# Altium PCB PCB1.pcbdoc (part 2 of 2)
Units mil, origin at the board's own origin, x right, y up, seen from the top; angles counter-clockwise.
Board outline 2755.9 x 2755.9 mil, 4 copper layers (Top Layer, GND02, PWR03, Bottom Layer), stack 64.1 mil thick; 209 components, 118 nets, 572 pads, 665 vias.
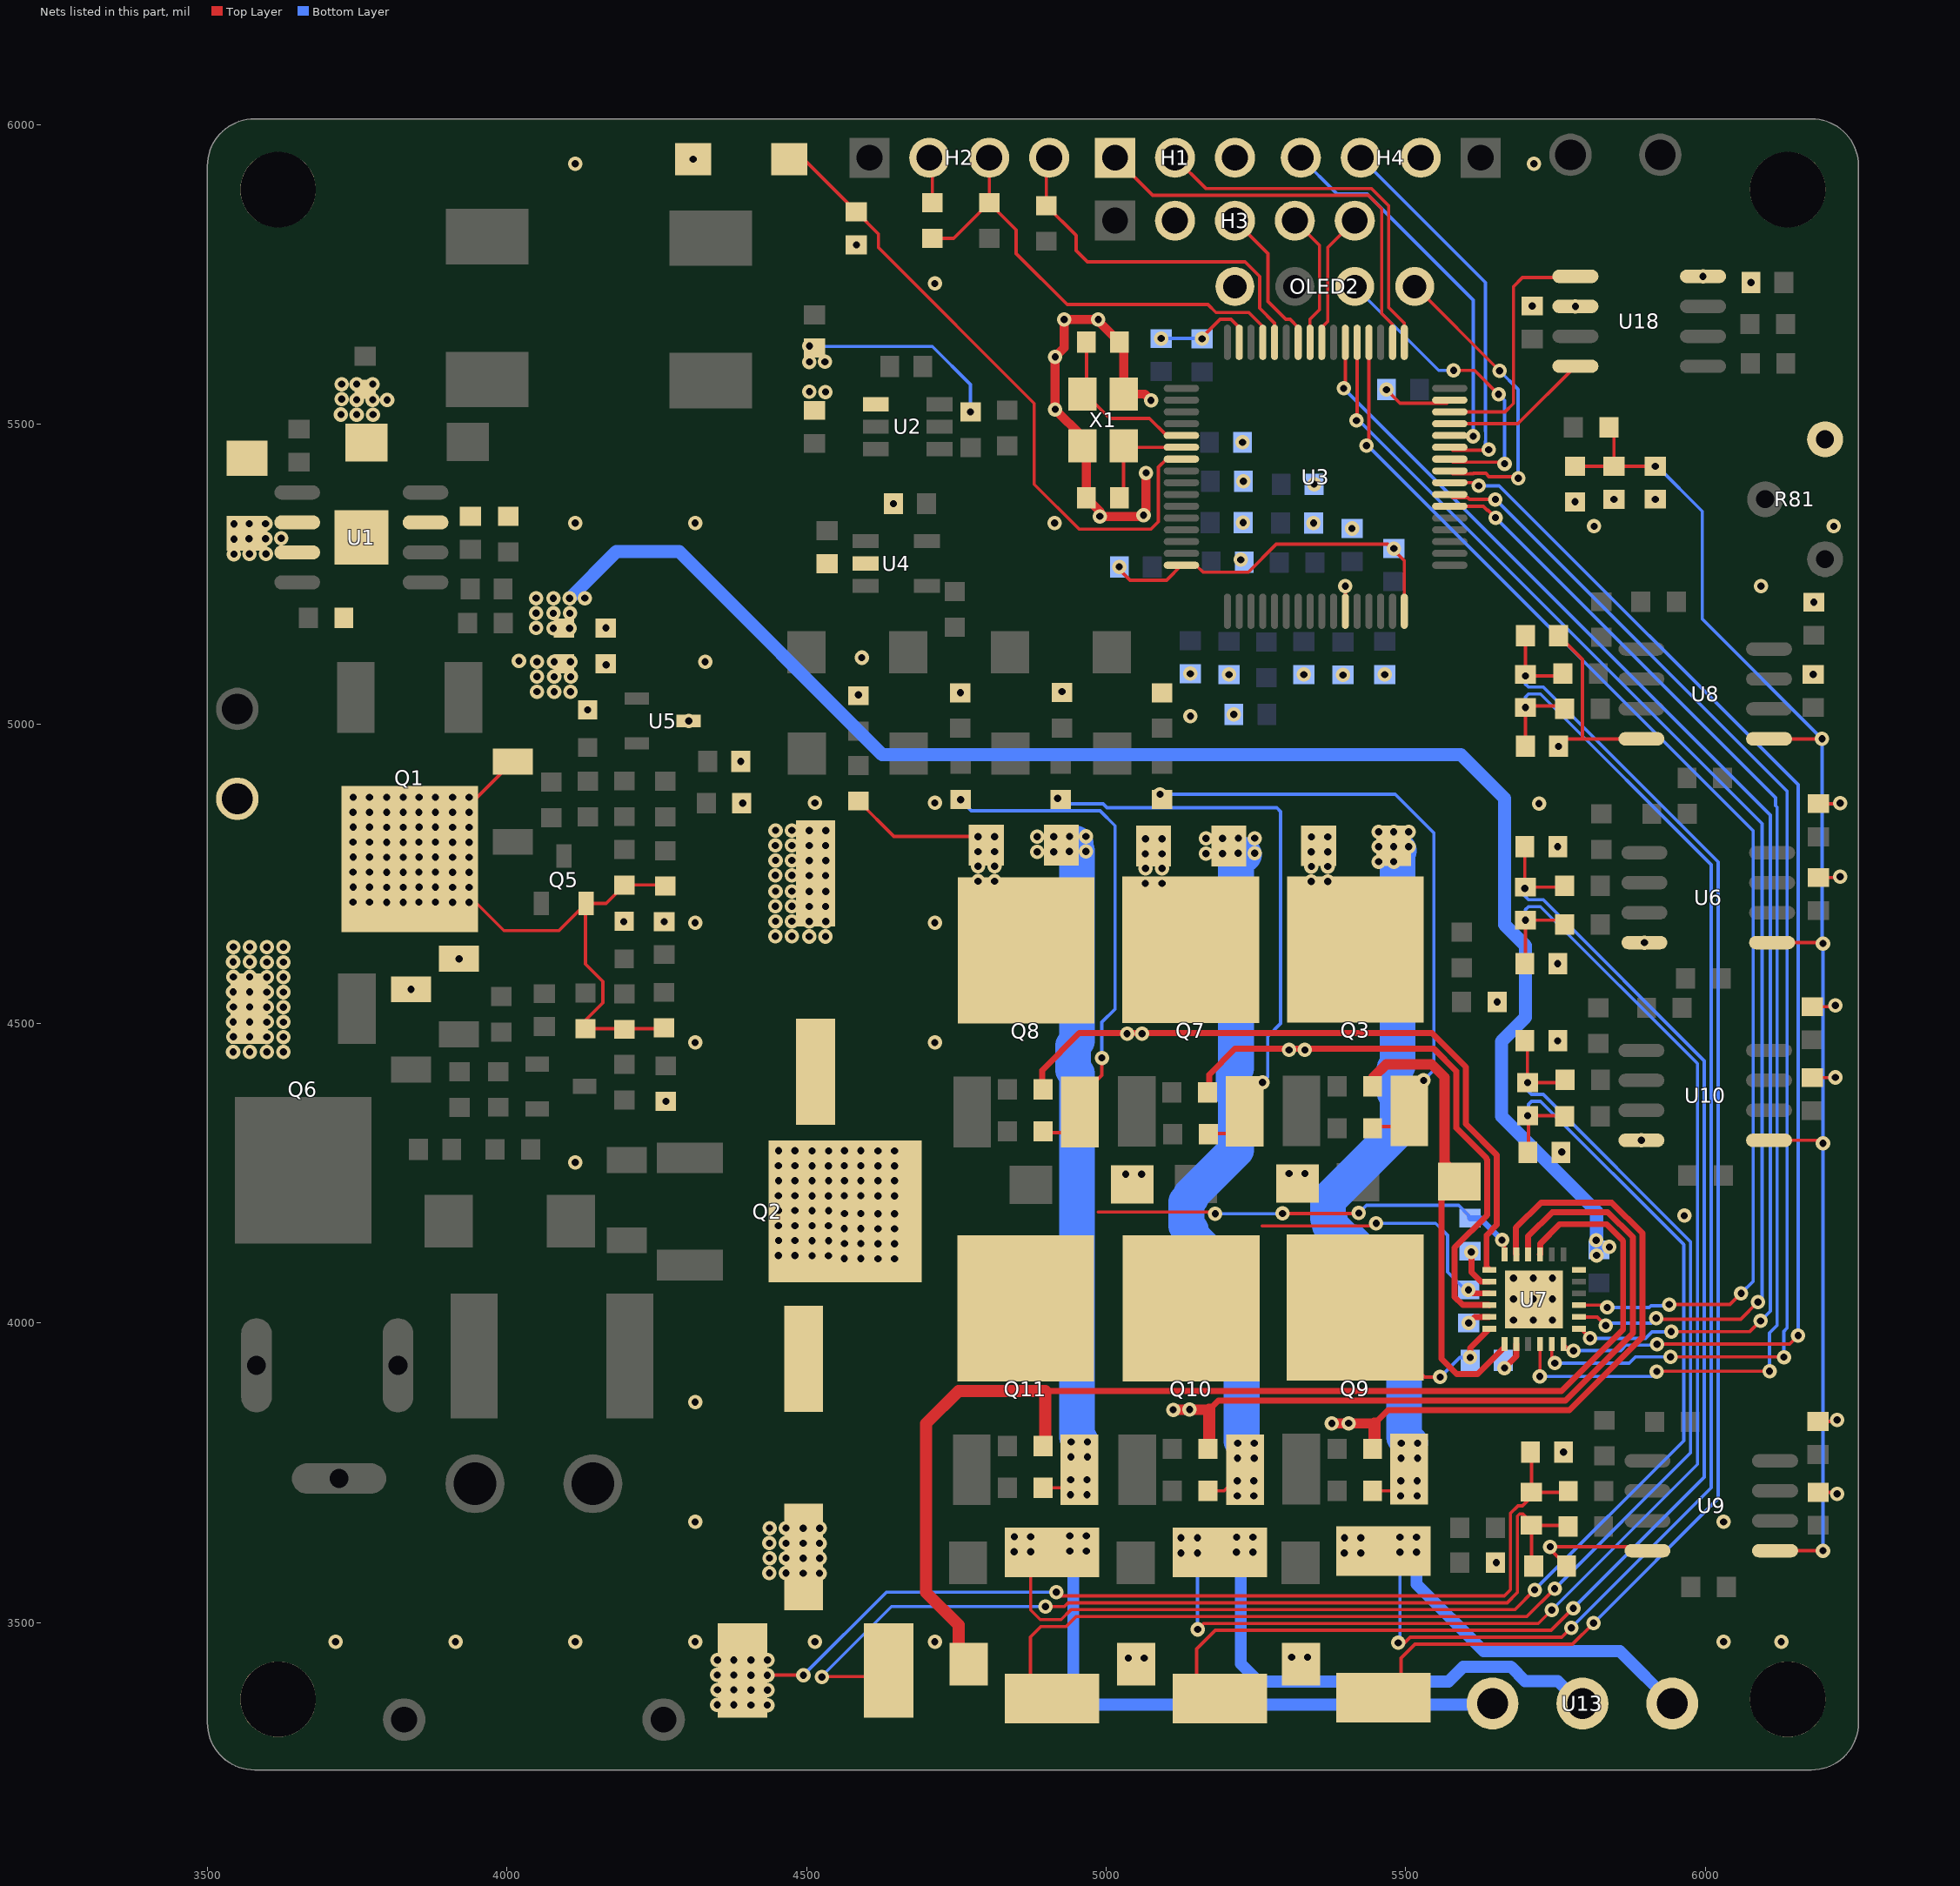
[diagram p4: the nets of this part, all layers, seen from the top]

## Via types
v1: diameter 24, hole 12, Top Layer to Bottom Layer, 665 vias

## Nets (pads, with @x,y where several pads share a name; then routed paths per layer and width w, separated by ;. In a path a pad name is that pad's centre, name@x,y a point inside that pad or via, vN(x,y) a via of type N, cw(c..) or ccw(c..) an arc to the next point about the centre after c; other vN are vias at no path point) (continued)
AGND: C18.2 C19.2 C21.1 C33.1 C34.1 C35.1 C36.1 C38.1 C39.1 C40.1 C41.1 C42.1 C44.1 C45.1 C46.1 C47.1 C48.1 C50.1 C51.1 C52.1 C53.1 C54.1 C56.1 C57.1 C58.1 C61.1 C63.1 C64.1 C68.1 C69.1 C70.1 R12.1 R37.1 R65.1 R67.1 R69.1 R71.1 R72.1 R73.1 R81.3 SCREW3.1 U3.27 U6.4 U8.4 U9.4 U10.4 | length 806
  Top Layer w5.5: U3.27@5399.3,5188.1 v1(5399.3,5230) ; v1(5755,4962.6) C45.1@5755.1,4962.7 ; C45.1@5755.1,4969.5 C45.1@5755.1,4962.7 ; C44.1@5755.1,5147.4 5795,5107.6 5795,4975 ; C39.1@5768.7,3594.6 5741.2,3622.1 v1(5741.2,3626.5) 5897,3626.5 U9.4@5903.5,3620 ; U8.4@5893.5,4975 5795,4975 ; C54.1@6178.7,4409.6 6216.8,4409.6 v1(6217.2,4410) ; C53.1@6178.7,4527.9 6215.1,4527.9 v1(6217.2,4530) ; C33.1@6188.4,3835.7 6219.3,3835.7 v1@6220,3835 ; C36.1@6188.5,3717.5 6217.5,3717.5 v1(6220,3715) ; C48.1@6188.7,4743.5 6223.5,4743.5 v1(6225,4745) ; C47.1@6188.7,4866.8 6223.2,4866.8 v1@6225,4865 ; C45.1@5755.1,4962.7 5767.4,4975 5795,4975
  other v1: 6030.7,3468.2 6126.9,3468.2 5651.3,3600 6030.7,3668.2 5763.5,3784.6 6220,3838.3 5965,4179.2 5760.5,4285.5 5893.5,4305 5753.8,4471.1 5652.7,4535.8 5753.8,4600 5898.5,4635 5753.8,4795 5722.5,4866.9 6225,4867.7 5140.8,5012.8 5213.3,5015.8 4586.5,5048.6 4756.7,5052 4926.3,5054 5205,5082.4 5330,5082.3 5395.3,5081.7 5465,5082.4 6180.1,5082.6 5140.4,5083.8 4330.8,5103.6 4592.2,5110.6 4165.1,5160.5 6181.2,5203.1 6092.9,5230 5224.8,5274 5410.4,5326.2 5814.6,5330 6214.6,5330 5346.3,5335.1 5228.7,5336.1 5782.7,5370.7 5847.6,5374.9 5916.6,5375 5347.2,5400.1 5229.2,5405 5227.7,5470
BSTA: C29.2 U7.20 | length 41
  Top Layer w10: v1@5670,3930 5684.7,3944.7 U7.20@5684.7,3964.9
  other v1: 5665,3925
BSTB: C30.1 U7.17 | length 38.5
  Top Layer w10: v1(5605.2,4000.1) 5615.3,4010.2 U7.17@5639.5,4010.2
BSTC: C31.1 U7.14 | length 70.1
  Top Layer w10: v1(5609.7,4118.6) 5609.7,4084.8 5625.3,4069.2 U7.14@5639.5,4069.2
DCBUS: C2.1 C5.1 C13.2 C59.1 C60.1 C62.1 D6.1 Q1.2 Q2.2 Q3.2 Q5.2 Q7.2 Q8.2 R8.2 R9.2 R10.2 R15.2 R23.2 R70.2 U1.2 U1.3 | length 1082.4
  Top Layer w5.5: v1(3936.7,4702.3) 3947.7,4702.3 3995,4655 4086.8,4655 Q5.2@4131,4699.3 ; v1(3936.7,4852.3) 3936.7,4863.6 D6.1@4010,4936.9 ; R8.2@4262.3,4492.6 4261,4491.4 R9.2@4131,4491.4 4131,4505.4 4160,4534.4 4160,4570 4131,4599 Q5.2@4131,4699.3 ; R23.2@4264.1,4729.2 4262.2,4731.1 R15.2@4195.9,4731.1 4165.5,4700.6 Q5.2@4132.4,4700.6 Q5.2@4131,4699.3 ; R70.2@4586.5,4871.3 4645.8,4812 v1(4786.4,4812)
  other v1: 4619.4,4107.3 4646.7,4107.3 4563,4107.6 4590.7,4107.6 4509.4,4112.3 4536.7,4112.3 4453,4112.6 4480.7,4112.6 4619.4,4132.4 4647,4132.4 4563.3,4132.7 4590.7,4132.7 4509.4,4137.4 4537,4137.4 4453.3,4137.7 4480.7,4137.7 4619.4,4157.3 4646.7,4157.3 4563,4157.6 4590.7,4157.6 4509.4,4162.3 4536.7,4162.3 4453,4162.6 4480.7,4162.6 4619.4,4182.4 4647,4182.4 4563.3,4182.7 4590.7,4182.7 4509.4,4187.4 4537,4187.4 4453.3,4187.7 4480.7,4187.7 4509.4,4212.3 4536.7,4212.3 4619.4,4212.3 4646.7,4212.3 4453,4212.6 4480.7,4212.6 4563,4212.6 4590.7,4212.6 4509.4,4237.4 4537,4237.4 4619.4,4237.4 4647,4237.4 4453.3,4237.7 4480.7,4237.7 4563.3,4237.7 4590.7,4237.7 4509.4,4262.3 4536.7,4262.3 4619.4,4262.3 4646.7,4262.3 4453,4262.6 4480.7,4262.6 4563,4262.6 4590.7,4262.6 4509.4,4287.4 4537,4287.4 4619.4,4287.4 4647,4287.4 4453.3,4287.7 4480.7,4287.7 4563.3,4287.7 4590.7,4287.7 3799.4,4702.3 3826.7,4702.3 3909.4,4702.3 3743,4702.6 3770.7,4702.6 3853,4702.6 3880.7,4702.6 3799.4,4727.4 3827,4727.4 3909.4,4727.4 3937,4727.4 3743.3,4727.7 3770.7,4727.7 3853.3,4727.7 3880.7,4727.7 5065.5,4733.7 5093.2,4733.7 4786.2,4737.4 4813.8,4737.4 5342.4,4736.9 5370.1,4736.9 3799.4,4752.3 3826.7,4752.3 3909.4,4752.3 3936.7,4752.3 3743,4752.6 3770.7,4752.6 3853,4752.6 3880.7,4752.6 5065.8,4758.8 5093.2,4758.8 5342.7,4762 5370.1,4762 4786.4,4762.6 4813.8,4762.6 3799.4,4777.4 3827,4777.4 3909.4,4777.4 3937,4777.4 3743.3,4777.7 3770.7,4777.7 3853.3,4777.7 3880.7,4777.7 5065.5,4783.2 5093.2,4783.2 5342.4,4786.3 5370.1,4786.3 4786.2,4786.9 4813.8,4786.9 3799.4,4802.3 3826.7,4802.3 3909.4,4802.3 3936.7,4802.3 3743,4802.6 3770.7,4802.6 3853,4802.6 3880.7,4802.6 5065.8,4808.3 5093.2,4808.3 5342.7,4811.4 5370.1,4811.4 4813.8,4812 3799.4,4827.4 3827,4827.4 3909.4,4827.4 3937,4827.4 3743.3,4827.7 3770.7,4827.7 3853.3,4827.7 3880.7,4827.7 3799.4,4852.3 3826.7,4852.3 3909.4,4852.3 3743,4852.6 3770.7,4852.6 3853,4852.6 3880.7,4852.6 3799.4,4877.4 3827,4877.4 3909.4,4877.4 3937,4877.4 3743.3,4877.7 3770.7,4877.7 3853.3,4877.7 3880.7,4877.7 3544.3,5283.2 3570.3,5283.6 3597.7,5283.6 3544.3,5308.3 3569.4,5309.1 3597.1,5309.1 3623.1,5309.8 3544.4,5333.7 3569.7,5334.2 3597.1,5334.2
FDCAN1_RX: U3.45 U18.4 | length 249.4
  Top Layer w5.5: U3.45@5573.6,5501.1 5687.3,5501.1 U18.4@5783.3,5597
FDCAN1_TX: U3.46 U18.1 | length 417.6
  Top Layer w5.5: U3.46@5573.6,5520.8 5665.8,5520.8 5680,5535 5680,5730 5695,5745 5781.3,5745 U18.1@5783.3,5747
GHA: D3.2 R84.1 U7.19 | length 778
  Top Layer w10: D3.2@5590.4,4224.2 5579.2,4224.2 5560,4205 5560,3940 5585,3915 5620,3915 5665.1,3960.1 U7.19@5665.1,3964.9
  Top Layer w17: R84.1@5446.5,4394.5 5446.5,4410.7 5467.7,4431.9 5543.1,4431.9 5565,4410 5565,4266.5 D3.2@5593,4238.4
GHB: D7.2 R61.1 U7.16 | length 957.1
  Top Layer w10: R61.1@5171.9,4387.8 5171.9,4414.7 5215.1,4457.9 5547.1,4457.9 5584.5,4420.5 5584.5,4325.5 5635,4275 5635,4273.7 5636.2,4272.5 5636.2,4180.2 5581.8,4125.8 5581.8,4043.6 5595.3,4030.1 5639.2,4030.1 U7.16@5639.5,4029.8
  other v1: 5305.5,4249.4 5332,4249.4 5305.2,4455.9 5331.7,4455.9
GHC: D8.2 R63.1 U7.13 | length 1155.4
  Top Layer w10: R63.1@4897.6,4393.1 4893.4,4397.2 4893.4,4421.9 4955.4,4483.8 4980.5,4483.8 ccw(c4980.5,4499.8) 4982.01,4483.87 ; 4982,4483.9 5543.7,4483.9 5600.5,4427.1 5600.5,4332.1 5652.2,4280.4 5652.2,4163.7 5635,4146.5 5635,4093.4 U7.13@5639.5,4088.9
  other v1: 5032.6,4248.5 5059.1,4248.5 5035,4483 5060,4483
GLA: D9.2 R75.1 U7.11 | length 1088.3
  Top Layer w10: 5447.9,3832.3 5470.3,3854.7 5773.3,3854.7 5895,3976.4 5895,4150 5844,4201 5726,4201 5684.2,4159.2 5684.2,4115 U7.11@5684.7,4114.5
  Top Layer w17: v1(5376.8,3832.3) 5447.9,3832.3
  Top Layer w20: R75.1@5447.9,3789.6 5447.9,3832.3
  other v1: 5309.7,3442.2 5336.2,3442.2 5405,3832.7
GLB: D10.2 R77.1 U7.10 | length 1280.3
  Top Layer w10: 5172.1,3855.3 5187.5,3870.7 5766.6,3870.7 5879,3983 5879,4143.4 5837.4,4185 5744.6,4185 5704.4,4144.9 U7.10@5704.4,4114.5
  Top Layer w17: v1(5111.9,3855.3) 5172.1,3855.3
  Top Layer w20: R77.1@5172.1,3794.2 5172.1,3855.3
  other v1: 5037.2,3440.8 5063.7,3440.8 5139.3,3855.8
GLC: D11.2 R79.1 U7.9 | length 2057
  Top Layer w10: 4898.3,3886.7 5760,3886.7 5863,3989.7 5863,4136.7 5834.7,4165 5757.1,4165 5724.4,4132.3 5724.4,4114.8 U7.9@5724.1,4114.5
  Top Layer w20: D11.2@4753.9,3438.6 4753.9,3495.8 4699.6,3550.1 4699.6,3832.5 4753.7,3886.7 4898.3,3886.7 R79.1@4898.3,3803.4
GND: C6.1 C9.1 C10.1 C12.1 C13.1 C14.1 C16.1 C17.1 C20.1 C22.1 C23.1 C24.1 C25.1 C26.2 C27.1 C28.1 C32.1 C67.1 D16.1 H1.3 H2.2 H3.2 H4.2 OLED2.1 R6.1 R11.1 R20.1 R22.1 R27.2 SCREW1.1 SCREW4.1 SW1.1 U1.7 U1.9 U2.1 U3.16 U3.32 U3.47 U3.63 U4.2 U7.6 U18.2 U18.8 X1.2 X1.4 | length 4709.8
  Top Layer w5.5: H2.2@4705,5945 4710,5940 R27.2@4710,5869.7 ; v1(5022,5262.2) 5022,5258 5040,5240 5100.8,5240 U3.16@5125.7,5264.9 5150.1,5264.9 5161.8,5253.3 5237.3,5253.3 5284,5300 5470,5300 5497.7,5272.3 U3.32@5497.7,5188.1 ; v1(5160,5642.8) 5160,5645 5190.2,5675.2 5208.5,5675.2 5222.2,5661.6 U3.63@5222.2,5636.9 ; v1(5468,5557.9) 5490.5,5535.4 5568.5,5535.4 U3.47@5573.6,5540.5
  Top Layer w15: v1(5066.7,5419) 5066.7,5356.7 v1@5058.2,5348.2 ; v1(5075,5540) 5064.4,5550.6 X1.4@5029.3,5550.6 5029.3,5630.6 C26.2@5022.3,5637.5 4986.9,5672.9 v1(4986.9,5675) v1(4930,5675) 4930,5627.7 v1(4915,5612.7) v1(4915,5525) 4960.4,5479.6 X1.2@4960.4,5464 4967,5457.4 C25.1@4967,5377.5 4989.6,5354.9 v1(4989.6,5346.5) 4989.8,5346.3 5056.3,5346.3 v1@5056.4,5346.4 ; v1@5056.4,5346.4 5060.7,5346.4 v1(5062.5,5348.2) v1@5058.2,5348.2 ; v1@5056.4,5346.4 v1@5058.2,5348.2
  Bottom Layer w5.5: v1@4515,5630 4710,5630 4773.7,5566.3 v1(4773.7,5520.9) ; v1(5092.1,5643.3) 5159.5,5643.3 v1(5160,5642.8)
  Bottom Layer w22: v1(4104.7,5209.7) 4182.5,5287.5 4287.5,5287.5 4626.4,4948.6 5592.1,4948.6 5665,4875.7 5665,4665 5700,4630 5700,4510 5660,4470 5660,4345 5818.6,4186.4 v1(5818.6,4113)
  other v1: 5840,4127 5818,4138.2 4048.7,5160 4077.4,5159.7 4104.7,5159.7 4048.7,5185.1 4077.4,5184.8 4105,5184.8 4048.7,5210 4077.4,5209.7 4130,5210 5480.3,5292.7 4114.1,5335.1 4314.1,5335.1 4914.1,5335.1 4645,5367.6 3722.9,5516.4 3749.2,5516.3 3776.6,5516.3 3749.2,5541 3776,5541 3800,5540.7 3724,5542.1 4504.9,5554.4 4531.7,5554.1 3724,5567.2 3749.2,5567.2 3776,5567.2 4504.9,5604.2 4530.9,5604.3 4504.9,5630.8 5783.3,5697 5711.3,5697.5 4714.1,5735.1 6076.2,5736.8 5996.3,5747 4583.2,5799.6 4114.1,5935.1 5714.1,5935.1 4310.8,5942.5
I2C1_SCL_Encoder&BOOT0: H2.3 R27.1 R31.1 U3.61 | length 185.9
  Top Layer w5.5: R27.1@4710,5810.3 4745.7,5810.3 R31.1@4805,5869.7 ; 4850,5785 4850,5824.7 ; U3.61@5261.5,5636.9 U3.61@5261.5,5663.5
I2C1_SCL_ENCODER&BOOT0:  | length 600.8
  Top Layer w5.5: 4805,5945 4805,5869.7 4850,5824.7 ; 4850,5785 4935,5700 5170,5700 5183.3,5686.7 5238.3,5686.7 5261.5,5663.5
I2C1_SDA_Encoder: H2.4 R30.1 U3.60 | length 364.7
  Top Layer w5.5: 4968.8,5771.2 5232.1,5771.2 5256.2,5747 ; 5256.2,5693.8 5281.2,5668.8 U3.60@5281.2,5636.9
I2C1_SDA_ENCODER:  | length 257.3
  Top Layer w5.5: 4905,5945 4900.3,5940.3 4900.3,5865 4950,5815.3 4950,5790 4968.8,5771.2 ; 5256.2,5693.8 5256.2,5747
I2C3_SCL_OLED: OLED2.3 U3.42 | length 529.2
  Top Layer w5.5: U3.42@5573.6,5442 5578.6,5437 5662.4,5437 v1(5665.1,5434.3) ; v1(5580,5590) 5615,5590 v1(5655,5550)
  Bottom Layer w5.5: OLED2.3@5415,5730.1 5555.1,5590 v1(5580,5590) ; v1(5655,5550) 5665.1,5539.9 v1(5665.1,5434.3)
I2C3_SDA_OLED: OLED2.4 U3.41 | length 512.2
  Top Layer w5.5: OLED2.4@5515,5730.1 5516.1,5730.1 v1(5656.8,5589.3) ; U3.41@5573.6,5422.3 5578.6,5417.3 5607.4,5417.3 5607.9,5417.8 5612.7,5417.8 5613.1,5418.3 5633.7,5418.3 5639.1,5412.8 5685.2,5412.8 v1(5687.8,5410.2)
  Bottom Layer w5.5: v1(5656.8,5589.3) 5687.8,5558.3 v1(5687.8,5410.2)
IA+: C43.1 C45.2 C62.2 Q9.3 R32.2 R64.1 R85.2 U13.3 | length 4110.1
  Top Layer w5.5: R64.1@5444.7,3720 5483.1,3720 v1(5491.6,3711.5) ; v1(5487.7,3466.3) 5498.3,3466.3 5507.6,3475.6 5760.6,3475.6 v1(5776.4,3491.4) ; C45.2@5699.9,4962.6 5700,4962.7 v1(5700,5027.4) ; C43.1@5700,5030 5760.3,5030 R85.2@5765.3,5025
  Bottom Layer w5.5: v1(5487.7,3466.3) 5490.5,3469.1 v1@5490.5,3612.4 ; v1@5700,5030 5700,5045 5705,5050 5725,5050 6010,4765 6010,3725 v1(5776.4,3491.4)
  Bottom Layer w20: v1(5518,3617.5) 5518,3564.3 5630,3452.3 5857.7,3452.3 U13.3@5945,3365
  Bottom Layer w60: v1@5488.7,4788.8 5486.4,4786.6 5486.4,4429.3 5482,4424.9 5482,4385.1 5486.4,4380.7 5486.4,4321.1 5370.3,4205 5370.3,4175 5373.8,4171.5 5373.8,4163.7 5401.9,4135.6 5409.7,4135.6 5497.5,4047.8 5497.5,3810 5507.5,3800
  other v1: 5397.6,3616.3 5425.3,3616.3 5490.3,3617.5 5397.9,3641.4 5425.3,3641.4 5490.6,3642.6 5518,3642.6 5519.3,3711.5 5491.8,3736.6 5519.3,3736.6 5492.2,3774.4 5519.9,3774.4 5492.5,3799.5 5519.9,3799.5 5455,4770 5480,4770 5455,4795 5480,4795 5505,4795 5455,4820 5480,4820 5505,4820
IA-: C37.1 C39.2 C43.2 C44.2 C49.2 C50.2 C55.2 C56.2 R32.1 R33.1 R34.1 R35.2 R46.2 R53.2 R56.2 R88.2 | length 8410
  Top Layer w5.5: v1@4525,3410 4627,3410 R35.2@4637,3420 ; R34.1@4873.7,3399.7 4873.7,3476.1 4891.1,3493.5 ; 4890.8,3493.5 4891.1,3493.5 ; v1(4898.7,3526.9) 4930.6,3526.9 4936.7,3533.1 5669.3,3533.1 5686.5,3550.2 5686.5,3677.8 5690.1,3681.4 5695.6,3681.4 5710,3667 C37.1@5710,3662.4 ; R33.1@5151,3410.4 5151,3456 5182.1,3487.1 5742.8,3487.1 v1(5779.8,3524.1) ; R32.1@5492.4,3405.1 5492.4,3440.8 5515.6,3464.1 5778.4,3464.1 v1(5813.7,3499.3) ; C49.2@5698.3,4725 v1(5698.7,4725.4) C50.2@5698.7,4795 ; C56.2@5698.7,4471.1 5703.3,4466.5 C55.2@5703.3,4400 ; C49.2@5700,4727.6 5762.9,4727.6 R46.2@5765.3,4730 ; C44.2@5700,5147.4 v1(5700,5080) 5758.2,5080 R88.2@5762.1,5083.9 ; v1(5703.6,4401.2) 5760.9,4401.2 R53.2@5765.8,4406.1 ; C39.2@5713.6,3594.6 5710,3598.2 C37.1@5710,3662.4 ; v1(5748.6,3556.4) 5702.2,3510.1 4950,3510.1 4933.4,3493.5 4891.1,3493.5 ; R56.2@5771,3660.7 5769.2,3662.4 C37.1@5710,3662.4
  Bottom Layer w5.5: v1@4525,3410 4641.9,3526.9 v1(4898.7,3526.9) ; v1@5698.3,4725 5698.3,4713.3 5705,4706.5 5729.8,4706.5 5998.5,4437.8 5998.5,3742.8 v1(5779.8,3524.1) ; v1(5700,5080) 5700,5066.5 5705,5061.5 5729.8,5061.5 6021.5,4769.8 6021.5,3707.1 v1(5813.7,3499.3) ; v1@5703.3,4400 5703.3,4388.3 5710,4381.5 5729.8,4381.5 5975.5,4135.8 5975.5,3783.4 v1(5748.6,3556.4)
  other v1: 4525.7,3409.1
IB+: C49.1 C51.2 C59.2 Q10.3 R33.2 R42.2 R76.1 U13.2 | length 4242.6
  Top Layer w5.5: v1(5152.8,3488.7) 5162.6,3498.6 5721.3,3498.6 v1(5743.9,3521.1) ; R76.1@5169.7,3720 5196.8,3720 Q10.3@5231.9,3755.1 ; C51.2@5698.7,4600 5700,4601.3 v1(5700,4672.4) ; C49.1@5700,4675 v1(5700,4672.4) ; R42.2@5765.3,4665 5757.9,4672.4 v1(5700,4672.4)
  Bottom Layer w5.5: v1(5152.5,3616.3) 5152.5,3489 v1(5152.8,3488.7) ; v1@5700,4675 5700,4690 5705,4695 5725,4695 5987,4433 5987,3764.2 v1(5743.9,3521.1)
  Bottom Layer w20: v1@5224.7,3612.9 5224.7,3431.2 5254.3,3401.6 5571.3,3401.6 5596,3426.3 5675.7,3426.3 5699.4,3402.5 5754,3402.5 U13.2@5790.5,3366.1
  Bottom Layer w60: v1@5229.8,4781.7 5224.8,4781.7 5216.9,4773.8 5216.9,4425.3 5213.1,4421.6 5213.1,4381.8 5216.9,4378 5216.9,4288.7 5141.5,4213.2 5141.5,4209.4 5134.2,4202.2 5134.2,4162.4 5141.5,4155.2 5141.5,4146.1 5226.3,4061.3 5226.3,3803.1 v1@5231.3,3798.1
  other v1: 5124.8,3616.3 5217.5,3617.5 5245.2,3617.5 5125.1,3641.4 5152.5,3641.4 5217.8,3642.6 5245.2,3642.6 5218.8,3711.5 5246.5,3711.5 5219,3736.6 5246.5,3736.6 5219.4,3774.4 5247.1,3774.4 5219.7,3799.5 5247.1,3799.5 5166.5,4783.7 5194.2,4783.7 5220.4,4784.1 5248.1,4784.1 5166.8,4808.8 5194.2,4808.8 5220.7,4809.2 5248.1,4809.2
IC+: C55.1 C57.2 C60.2 Q11.3 R34.2 R48.2 R78.1 U13.1 | length 4128
  Top Layer w5.5: R34.2@4874.1,3581.3 4874.1,3520.9 4890,3505 4924.9,3505 4941.5,3521.6 5682.1,3521.6 v1(5715.3,3554.7) ; R78.1@4894.7,3725 4925.6,3725 Q11.3@4955.7,3755.1 ; v1(5703.6,4346.1) 5764.2,4346.1 R48.2@5765.3,4345 ; C57.2@5703.9,4284.6 5705,4285.7 C55.1@5705,4345
  Bottom Layer w5.5: v1@5705,4345 5705,4365 5710,4370 5725,4370 5964,4131 5964,3803.4 v1(5715.3,3554.7)
  Bottom Layer w20: v1@4945.3,3617.8 4945.3,3387.8 4969.9,3363.1 5638.4,3363.1 U13.1@5642.4,3367.1
  Bottom Layer w60: 4948.7,4800.7 4948.7,4790.7 4951.4,4788 4951.4,4470.9 4947.9,4467.5 4947.9,4465.4 4944.9,4462.4 4944.9,4422.6 4951.4,4416.1 4951.4,3809.9 4956.4,3804.9
  other v1: 4846.6,3618.3 4874.3,3618.3 4939.3,3619.5 4967,3619.5 4846.9,3643.4 4874.3,3643.4 4939.6,3644.7 4967,3644.7 4940.6,3713.5 4968.3,3713.5 4940.8,3738.6 4968.3,3738.6 4941.2,3776.4 4968.9,3776.4 4941.5,3801.5 4968.9,3801.5 4884.9,4786.6 4912.5,4786.6 4938.8,4787.1 4966.5,4787.1 4885.1,4811.8 4912.5,4811.8 4939,4812.2 4966.5,4812.2
INHA: U3.38 U7.22 | length 2150.2
  Top Layer w5.5: U3.38@5573.6,5363.3 5601.7,5363.3 5601.8,5363.2 5629.7,5363.2 5636,5356.9 5637.4,5356.9 v1(5650,5344.3) ; v1(5723.9,3910.8) 5724.1,3911 U7.22@5724.1,3964.9 ; v1(5919.1,3919.2) 5919.4,3919.5 v1(6107.3,3919.5)
  Bottom Layer w5.5: v1(5650,5344.3) 6117.3,4877 6117.3,4863.9 6120,4861.2 6120,3996.3 6107.3,3983.6 v1(6107.3,3919.5) ; v1(5723.9,3910.8) 5910.6,3910.8 v1(5919.1,3919.2)
INHB: U3.39 U7.23 | length 2135.8
  Top Layer w5.5: U3.39@5573.6,5383 5578.6,5377.9 5603.3,5377.9 5606.5,5374.7 v1(5649.7,5374.7) ; U7.23@5743.8,3964.9 5743.8,3938.5 v1(5749.1,3933.1) ; v1(5942,3943.6) 6130.7,3943.6 v1(6131.2,3943.1)
  Bottom Layer w5.5: v1(5649.7,5374.7) 6136.7,4887.7 6136.7,3991.7 6131.2,3986.2 v1(6131.2,3943.1) ; v1(5749.1,3933.1) 5873.1,3933.1 5883.6,3943.6 v1(5942,3943.6)
INHC: U3.40 U7.24 | length 2103.2
  Top Layer w5.5: U3.40@5573.6,5402.7 5616.6,5402.7 v1(5621.7,5397.5) ; U7.24@5763.5,3964.9 5774.5,3953.9 v1(5780,3953.9) ; 5932.5,3965 6140.9,3965 v1(6155,3979.2)
  Bottom Layer w5.5: v1(5621.7,5397.5) 5656.1,5397.5 6155,4898.6 v1(6155,3979.2) ; v1(5780,3953.9) 5858.9,3953.9 5868.1,3963.1 5918.3,3963.1 v1(5919.7,3964.5)
INLA: U3.54 U7.1 | length 2257.8
  Top Layer w5.5: v1(5396.6,5560) 5399.3,5562.8 U3.54@5399.3,5636.9 ; U7.1@5789.1,3990.5 5792.1,3990.5 v1(5807.9,3974.6) ; v1(5943.3,3985.8) 6074.5,3985.8 v1(6092.3,4003.6)
  Bottom Layer w5.5: v1(5396.6,5560) 6108.5,4848 6108.5,4019.8 v1(6092.3,4003.6) ; v1(5807.9,3974.6) 5900.5,3974.6 5911.1,3985.3 5942.8,3985.3 v1(5943.3,3985.8)
INLB: U3.53 U7.2 | length 2210.5
  Top Layer w5.5: v1(5417.8,5506.3) 5419,5507.5 U3.53@5419,5636.9 ; U7.2@5789.1,4010.1 5819.7,4010.1 v1(5833.8,3996) ; v1(5918,4008.2) 5919.7,4006.5 6059.2,4006.5 v1(6087.8,4035.1)
  Bottom Layer w5.5: v1(5417.8,5506.3) 5422.2,5506.3 6095,4833.6 6095,4042.2 v1(6087.8,4035.1) ; v1(5833.8,3996) 5837.8,4000 5909.7,4000 v1(5918,4008.2)
INLC: U3.52 U7.3 | length 2145.8
  Top Layer w5.5: v1@5435.8,5465.8 5438.7,5468.7 U3.52@5438.7,5636.9 ; U7.3@5789.1,4029.8 5832.6,4029.8 v1(5836.4,4026) ; v1(5940,4030.9) 6041.2,4030.9 v1(6060,4049.7)
  Bottom Layer w5.5: v1@5435.8,5465.8 6080,4821.5 6080,4069.7 v1(6060,4049.7) ; v1(5836.4,4026) 5906.4,4026 5909.4,4029 5938.1,4029 v1(5940,4030.9)
  other v1: 5434.6,5464.6
MA: C29.1 Q3.3 Q9.2 R58.2 R59.1 U7.18 | length 1275.9
  Top Layer w5.5: Q9.2@5415.8,4025.7 5531.6,3909.9 v1(5557.6,3909.9) ; R59.1@5448.3,4327.8 5504.2,4327.8 Q3.3@5505.4,4328.9
  Top Layer w10: v1(5607.7,3942.6) 5607.7,3958.7 U7.18@5639.5,3990.5
  Bottom Layer w5.5: v1(5090,4882.5) 5482.5,4882.5 5547.2,4817.8 5547.2,4422.2 v1(5530,4405) ; v1(5557.6,3909.9) 5590.3,3942.6 v1(5607.7,3942.6)
MB: C30.2 Q7.3 Q10.2 R60.1 R66.2 U7.15 | length 1358.6
  Top Layer w5.5: R60.1@5177.1,4316.5 5223.9,4316.5 Q7.3@5224.5,4315.8 ; 5260.5,4162.2 5446.6,4162.2 v1(5450.8,4166.4)
  Top Layer w10: v1(5604.8,4055.4) 5610.6,4049.5 U7.15@5639.5,4049.5
  Bottom Layer w5.5: v1(4919.3,4875.7) 4928.5,4866.5 4994.8,4866.5 5001.3,4860 5285,4860 5291.4,4853.6 5291.4,4500 5269.8,4478.4 5269.8,4410.4 v1(5261.1,4401.7) ; v1(5450.8,4166.4) 5550,4166.4 5570,4146.4 5570,4085 5599.6,4055.4 v1(5604.8,4055.4)
MC: C31.2 Q8.3 Q11.2 R62.1 R68.2 U7.12 | length 1507.9
  Top Layer w5.5: R62.1@4895.4,4317.8 4943.4,4317.8 Q8.3@4944.1,4317.1 ; Q8.3@4973.5,4394.3 4992.9,4413.8 v1(4992.9,4442.5) ; 4986.7,4185.4 5179.1,4185.4 v1@5181,4183.4 ; v1@5181,4185.4 v1@5181,4183.4 ; v1(5182.2,4182.3) v1@5181,4183.4 ; v1(5294.4,4182.9) 5421.1,4182.9 v1(5421.8,4183.6) ; v1(5660.8,4138.5) 5665.1,4134.2 U7.12@5665.1,4114.5
  Bottom Layer w5.5: v1@4760,4870 4775,4855 4990,4855 5015,4830 5015,4524.1 4992.9,4502 v1(4992.9,4442.5) ; v1(5182.2,4182.3) 5293.8,4182.3 v1(5294.4,4182.9) ; v1(5421.8,4183.6) 5434.7,4196.5 5588.5,4196.5 5605,4180 5605,4177.4 C31.2@5607.4,4175
  Bottom Layer w10: C31.2@5607.5,4175 5624.2,4175 v1(5660.8,4138.5)
  other v1: 4757.4,4873.7
PF0-OSC_IN: C26.1 U3.5 X1.1 | length 283.7
  Top Layer w5.5: C26.1@4967.2,5637.5 4967.2,5557.4 X1.1@4960.4,5550.6 4965.7,5550.6 5006.3,5510 5072.4,5510 5101,5481.4 U3.5@5125.7,5481.4
PF1-OSC_OUT: C25.2 U3.6 X1.3 | length 186.9
  Top Layer w5.5: C25.2@5022.1,5377.5 5029.3,5384.7 X1.3@5029.3,5464 5031.5,5461.7 U3.6@5125.7,5461.7
PG10-NRST: C6.2 SW1.2 U3.7 | length 1104.7
  Top Layer w5.5: SW1.2@4471.1,5942.5 4495.5,5942.5 C6.2@4583.2,5854.7 4620,5817.9 4620,5795 4880,5535 4880,5400 4955,5325 5075,5325 5087.4,5337.4 5087.4,5428.4 5101,5442 U3.7@5125.7,5442
PGND: C2.2 C4.1 C5.2 C7.1 C37.2 C38.2 CN2.2 D1.2 D5.2 LED1.1 LED2.1 Q6.3 R5.1 R11.2 R12.2 R24.1 R35.1 R57.2 SCREW2.1 U5.3 U7.25 | length 1616
  Top Layer w5.5: v1@4434.7,3412.3 v1(4494.8,3412.3) ; v1(4917.1,3550.9) 4923.4,3544.6 5664.6,3544.6 5675,3555 5675,3682.6 5687.4,3695 5695,3695 5710,3710 C37.2@5710,3717.6 ; C38.2@5708.4,3784.6 5710,3782.9 C37.2@5710,3717.6 ; R57.2@5771.4,3719.6 5769.4,3717.6 C37.2@5710,3717.6
  Bottom Layer w5.5: v1(4494.8,3412.3) 4633.4,3550.9 v1(4917.1,3550.9)
  other v1: 4407.3,3362.3 4434.6,3362.3 4351,3362.6 4378.7,3362.6 4407.3,3387.4 4434.9,3387.4 4351.3,3387.7 4378.7,3387.7 4407.3,3412.3 4434.6,3412.3 4351,3412.6 4378.7,3412.6 4407.3,3437.4 4434.9,3437.4 4351.3,3437.7 4378.7,3437.7 3714.1,3468.2 3914.1,3468.2 4114.1,3468.2 4314.1,3468.2 4514.1,3468.2 4714.1,3468.2 4494.4,3582.3 4521.7,3582.3 4438,3582.6 4465.7,3582.6 4494.4,3607.4 4522,3607.4 4438.3,3607.7 4465.7,3607.7 4494.4,3632.3 4521.7,3632.3 4438,3632.6 4465.7,3632.6 4494.4,3657.4 4522,3657.4 4438.3,3657.7 4465.7,3657.7 4314.1,3668.2 4314.1,3868.2 5680,4005 5713,4005 5745,4005 5680,4040 5713,4040 5745,4040 5680,4075 5713,4075 5745,4075 4114.1,4268.2 4265.3,4370 4314.1,4468.2 4714.1,4468.2 3599.4,4552.3 3626.7,4552.3 3543,4552.6 3570.7,4552.6 3840,4556.9 3599.4,4577.4 3627,4577.4 3543.3,4577.7 3570.7,4577.7 3599.4,4602.3 3626.7,4602.3 3543,4602.6 3570.7,4602.6 3920,4608 3599.4,4627.4 3627,4627.4 3543.3,4627.7 3570.7,4627.7 4504.4,4645.2 4531.7,4645.2 4448,4645.5 4475.7,4645.5 4314.1,4668.2 4714.1,4668.2 4195,4670 4262.4,4670 4504.4,4670.3 4532,4670.3 4448.3,4670.6 4475.7,4670.6 4504.4,4695.2 4531.7,4695.2 4448,4695.5 4475.7,4695.5 4504.4,4720.3 4532,4720.3 4448.3,4720.6 4475.7,4720.6 4448,4747.1 4475.7,4747.1 4504.4,4746.8 4531.7,4746.8 4448.3,4772.2 4475.7,4772.2 4504.4,4771.9 4532,4771.9 4448,4797.1 4475.7,4797.1 4504.4,4796.8 4531.7,4796.8 4448.3,4822.2 4475.7,4822.2 4504.4,4821.9 4532,4821.9 4393.6,4867.8 4514.1,4868.2 4714.1,4868.2 4390.1,4937.6 4303.4,5005 4134.6,5023.5 4050.2,5053.8 4078.8,5053.6 4106.1,5053.6 4050.2,5078.9 4078.8,5078.7 4106.4,5078.7 4165.7,5098.7 4050.2,5103.8 4078.8,5103.6 4106.1,5103.6 4020,5105
pgnd: 
  other v1: 3599.4,4452.3 3626.7,4452.3 3543,4452.6 3570.7,4452.6 3599.4,4477.4 3627,4477.4 3543.3,4477.7 3570.7,4477.7 3599.4,4502.3 3626.7,4502.3 3543,4502.6 3570.7,4502.6 3599.4,4527.4 3627,4527.4 3543.3,4527.7 3570.7,4527.7
SPI1_MISO_Encoder: H3.4 U3.57 | length 226.8
  Top Layer w5.5: H3.4@5315,5840 5356.2,5798.8 5356.2,5691.2 5340.3,5675.3 U3.57@5340.3,5636.9
SPI1_MISO_ENCODER: 
SPI1_MOSI_Encoder: H3.3 U3.58 | length 24.7
  Top Layer w5.5: U3.58@5320.6,5636.9 U3.58@5320.6,5661.6
SPI1_MOSI_ENCODER:  | length 226.4
  Top Layer w5.5: 5215,5840 5270,5785 5270,5705 5299.8,5675.2 5307,5675.2 5320.6,5661.6
SPI1_SCK_Encoder: H3.5 U3.56 | length 226
  Top Layer w5.5: U3.56@5359.9,5636.9 5359.9,5661.6 5370,5671.6 5370,5795 H3.5@5415,5840
SPI1_SCK_ENCODER: 
SWCLK: H1.1 U3.50 | length 710.8
  Top Layer w5.5: H1.1@5015,5945 5077.8,5882.2 5437.8,5882.2 5460,5860 5460,5685 5478.1,5666.9 U3.50@5478.1,5636.9
SWDIO: H1.2 U3.49 | length 628.5
  Top Layer w5.5: H1.2@5115,5945 5166.3,5893.7 5442.6,5893.7 5471.5,5864.8 5471.5,5695 5497.7,5668.8 U3.49@5497.7,5636.9
USART1_RX: H4.4 U3.44 | length 655.5
  Top Layer w5.5: U3.44@5573.6,5481.4 5574.9,5480.1 v1(5612.7,5480.1) 5613.1,5480.5 v1@5615,5480.5
  Bottom Layer w5.5: H4.4@5325,5945 5385,5885 5435,5885 5612.7,5707.3 v1(5612.7,5480.1)
USART1_TX: H4.3 U3.43 | length 643
  Top Layer w5.5: U3.43@5573.6,5461.7 5578.6,5456.7 5634.3,5456.7 5635.4,5457.7 v1(5638.4,5457.7)
  Bottom Layer w5.5: H4.3@5425,5945 5633.3,5736.7 5633.3,5488.8 5633.4,5488.7 5633.4,5471.5 5633.3,5471.4 5633.3,5462.8 v1(5638.4,5457.7)
VREF: C34.2 C35.2 R36.1 R37.2 U6.5 U8.5 U9.5 U10.5 | length 2470.7
  Top Layer w5.5: R37.2@5782.7,5430 C34.2@5847.6,5430 ; R36.1@5839.3,5494.7 5847.6,5486.4 C34.2@5847.6,5430 ; v1(5916.6,5430.1) 5916.4,5430 C34.2@5847.6,5430 ; U10.5@6106.5,4305 6191.5,4305 v1(6196.5,4300) ; U8.5@6106.5,4975 v1(6195,4975) ; U6.5@6111.5,4635 v1@6195,4635 ; U9.5@6116.5,3620 v1(6196.5,3620)
  Bottom Layer w5.5: v1@5920,5430 5995,5355 5995,5175 v1(6195,4975) 6195,4635 v1(6196.5,4633.5) v1(6196.5,4300) v1(6196.5,3620)
pads on no net: CN1.3 CN1.4 U3.2 U3.3 U3.4 U3.11 U3.17 U3.23 U3.24 U3.25 U3.26 U3.30 U3.33 U3.34 U3.35 U3.36 U3.37 U3.51 U3.55 U3.59 U3.62 U4.4 U7.5 U7.7 U7.8 U7.21 U18.5

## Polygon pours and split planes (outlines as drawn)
GND on Top Layer (solid, remove dead copper, pour order 0): 6355,5520 5765.7,5520 5659.1,5413.4 5476,5413.4 5368.8,5520.5 5368.6,5520.3 5189.8,5520.3 5145.2,5475.7 5145.2,5269.8 5150.1,5264.9 5145,5264.9 5064.4,5184.2 4146.6,5184.2 4126.8,5164.3 4127,5164.1 4127,5131.1 3708.9,5131.1 3705,5135 3705,5345 3683.6,5366.4 3682.2,5365 3429.6,5365 3429.6,6219.6 3435,6225 6450,6225 6450,5615
AGND on Top Layer (solid, remove dead copper, pour order 2): 6301.8,5519.1 6570,5250.9 6570,3210 6518.7,3158.7 6020,3158.7 6020,3432.4 5976.9,3475.6 5636.2,3475.6 5636.2,3476 5560.3,3551.9 5560.3,3801.3 5596.7,3837.7 5779.9,3837.7 5910.2,3968 5910.2,4157 5850.3,4216.8 5696.9,4216.8 5666.6,4247.1 5666.6,4288.4 5614.2,4340.8 5614.2,4435.8 5561,4489 5561,4824 5485.4,4899.6 4460.4,4899.6 4230,5130 4127.9,5130 4126.8,5131.1 4126.8,5164.3 4146.6,5184.2 5064.3,5184.2 5064.4,5184.1 5144.5,5264.1 5144.5,5474.6 5189.8,5520 5370,5520 5370,5519.3 5476,5413.3 5659,5413.3 5764.8,5519.1
GND on Bottom Layer (solid, remove dead copper, pour order 6): 6355,5520 5765.7,5520 5659.1,5413.4 5476,5413.4 5368.8,5520.5 5368.6,5520.3 5189.8,5520.3 5145.2,5475.7 5145.2,5269.8 5150.1,5264.9 5145,5264.9 5064.4,5184.2 4146.6,5184.2 4126.8,5164.3 4127,5164.1 4127,5131.1 3708.9,5131.1 3705,5135 3705,5345 3683.6,5366.4 3682.2,5365 3429.6,5365 3429.6,6219.6 3435,6225 6450,6225 6450,5615
AGND on Bottom Layer (solid, remove dead copper, pour order 6): 6301.8,5519.1 6570,5250.9 6570,3210 6518.7,3158.7 6020,3158.7 6020,3432.4 5976.9,3475.6 5636.2,3475.6 5636.2,3476 5560.3,3551.9 5560.3,3801.3 5596.7,3837.7 5779.9,3837.7 5910.2,3968 5910.2,4157 5850.3,4216.8 5696.9,4216.8 5666.6,4247.1 5666.6,4288.4 5614.2,4340.8 5614.2,4435.8 5561,4489 5561,4824 5485.4,4899.6 4460.4,4899.6 4230,5130 4127.9,5130 4126.8,5131.1 4126.8,5164.3 4146.6,5184.2 5064.3,5184.2 5064.4,5184.1 5144.5,5264.1 5144.5,5474.6 5189.8,5520 5370,5520 5370,5519.3 5476,5413.3 5659,5413.3 5764.8,5519.1
PGND on Top Layer (solid, remove dead copper, pour order 6): 3405,5365 3682.7,5365 3700.8,5346.9 3700.8,5140.2 3705,5136 3705,5135 3710,5130 4230,5130 4459.2,4900.8 5485,4900.8 5485,4900 5561,4824 5561,4489 5615,4435 5615,4340 5666.1,4288.9 5666.1,4247.2 5696.5,4216.8 5850.3,4216.8 5910.6,4156.6 5910.6,3970.6 5779.7,3839.7 5596.7,3839.7 5596.7,3837.9 5560,3801.2 5560,3551.9 5636.4,3475.6 5636.7,3475.6 5637.3,3475 5976.9,3475 6019,3432.9 6019,3140 3140,3140 3000,3000 3000,4960
PGND on Bottom Layer (solid, remove dead copper, pour order 10): 3405,5365 3682.7,5365 3700.8,5346.9 3700.8,5140.2 3705,5136 3705,5135 3710,5130 4230,5130 4459.2,4900.8 5485,4900.8 5485,4900 5561,4824 5561,4489 5615,4435 5615,4340 5666.1,4288.9 5666.1,4247.2 5696.5,4216.8 5850.3,4216.8 5910.6,4156.6 5910.6,3970.6 5779.7,3839.7 5596.7,3839.7 5596.7,3837.9 5560,3801.2 5560,3551.9 5636.4,3475.6 5636.7,3475.6 5637.3,3475 5976.9,3475 6019,3432.9 6019,3140 3140,3140 3000,3000 3000,4960

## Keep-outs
GND02:
  region: 4948.1,3761.3 4948.1,3755.4 4959.7,3755.4 4959.7,3761.3
  region: 5227,3760.7 5227,3751.6 5238.5,3751.6 5238.5,3760.7
  region: 5501.9,3760.3 5501.9,3752.3 5510.7,3752.3 5510.7,3760.3
  region: 3549.1,5358.5 3549.1,5349.8 3562.6,5349.8 3562.6,5358.5
  region: 3576.1,5358.5 3576.1,5349.1 3591.1,5349.1 3591.1,5358.5
  region: 5916.9,4018.6 5916.9,4000.7 5928.5,4000.7 5928.5,4018.6
  region: 5916.8,3982 5916.8,3975 5923.8,3975 5923.8,3982
  region: 4542.9,5468.3 4542.9,5461.1 4550,5461.1 4550,5468.3
  region: 4227.4,5189.3 4227.4,5185.2 4235,5185.2 4235,5189.3
  region: 4257.1,5188.3 4257.1,5184.4 4263.2,5184.4 4263.2,5188.3
  region: 5728.5,3544 5728.5,3535.7 5738.2,3535.7 5738.2,3544
  region: 5759.9,3512 5759.9,3504.9 5767.3,3504.9 5767.3,3512
PWR03:
  region: 4132.7,5135.1 4132.3,5135.5 4132.3,5163.7 4147.7,5179 4149,5177.7 4165.1,5177.7 4167.9,5174.9 4167.9,5133.6 4166.5,5135.1
  region: 5931.3,4019 5931.3,4009.7 5917.7,3996.2 5917.7,4023.6 5918.3,4024.2 5923.5,4019
  region: 5923.5,3976 5924.3,3975.2 5924.3,3972.4 5913.7,3972.4 5913.6,3972.5 5913.8,3972.7 5913.8,3981 5914.4,3981.6 5923.6,3981.6 5923.5,3981.6
  region: 6212.6,5308.2 6212.6,5314.4 6220,5321.8 6229.6,5321.8 6233.3,5318 6233.3,5305.8 6228.1,5300.6 6220.2,5300.6
  region: 4948.5,3759.1 4948.8,3759.1 4954.6,3765 4962.6,3757.1 4962.6,3757 4957.3,3751.8 4955.1,3751.8 4955.1,3752.5
  region: 5228.5,3758.3 5228.5,3751.5 5236.7,3751.5 5236.7,3758.3
  region: 5503.1,3759.2 5503.1,3752.4 5510.3,3752.4 5510.3,3759.2
  region: 5691,4061.6 5691,4052.3 5701.3,4052.3 5701.3,4061.6
  region: 5689.6,4027 5689.6,4018 5702.3,4018 5702.3,4027
  region: 5724.2,4061 5724.2,4053.2 5732.6,4053.2 5732.6,4061
  region: 5724.9,4026.2 5724.9,4016.6 5733.8,4016.6 5733.8,4026.2
  region: 4057,5143.7 4057,5137.7 4069.5,5137.7 4069.5,5143.7
  region: 4085.5,5143.3 4085.5,5137.9 4096.4,5137.9 4096.4,5143.3
  region: 4113,5150.3 4113,5139.8 4125,5139.8 4125,5150.3
  region: 5728.5,3543.9 5728.5,3534.7 5737.3,3534.7 5737.3,3543.9
  region: 5760.5,3512 5760.5,3504.6 5767.3,3504.6 5767.3,3512
  region: 4716.3,4894.7 4716.3,4872.4 4743.6,4872.4 4743.6,4894.7
Board Outline Layer:
  region: 3826.7,5844.1 3826.7,5544.1 4106.7,5544.1 4106.7,5844.1
  region: 4210.4,5837.6 4210.4,5546.3 4470.2,5546.3 4470.2,5837.6
  region: 5155,5490 5155,5455 5065,5455 5060,5450 5060,5370 5045,5355 5005,5355 4995,5365 4995,5490 4972.7,5512.3 4942.6,5512.3 4929.8,5525 4929.8,5597.3 4945,5612.5 4945,5655 4950,5660 4985,5660 4989.8,5655.2 4989.8,5535.1 5009.9,5515 5075,5515 5100,5490
  lines w10: 3500,3332.8 3500,5931.3 cw(c3578.7,5931.3) 3578.7,6010 6177.2,6010 cw(c6177.2,5931.3) 6255.9,5931.3 6255.9,3332.8 cw(c6177.2,3332.8) 6177.2,3254.1 3578.7,3254.1 cw(c3578.7,3332.8) 3500,3332.8 ; 3500,3332.8 3500,3332.8

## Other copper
Top Layer:
  drawing of 611 lines, arcs and shapes, not listed
Bottom Layer:
  drawing of 161 lines, arcs and shapes, not listed
GND02 (plane layer: these items are gaps in the copper):
  lines w5.5: 4127,5131.1 4127,5164.6 4146.6,5184.2 5064.4,5184.2 5144.3,5264.1 5144.3,5474.8 5189.8,5520.3 5369,5520.3 5476,5413.4 5659.1,5413.4 5764.8,5519.1 6346.1,5519.1 6349.1,5522.1
  lines w20: 3405,5365 3682.7,5365 3699.5,5348.2 3699.5,5140.2 3709.7,5130 4230,5130 4460,4900 5484.6,4900 ; 5485,4900 5561,4824 5561,4489 5615,4435 5615,4340 ; 5615,4339.4 5666.6,4287.8 5666.6,4247.2 5696.9,4216.8 5738.4,4216.8 5850.3,4216.8 5910.3,4156.8 5910.3,3968 5780.3,3837.9 5596.7,3837.9 5560,3801.2 5560,3551.9 5636.9,3475 5976.9,3475 6020,3431.9 6020,3158.7
PWR03 (plane layer: these items are gaps in the copper):
  lines w5.5: 4127,5131.1 4127,5164.6 4146.6,5184.2 5064.4,5184.2 5144.3,5264.1 5144.3,5474.8 5189.8,5520.3 5369,5520.3 5476,5413.4 5659.1,5413.4 5764.8,5519.1 6346.1,5519.1 6349.1,5522.1 ; 4210.4,6060 4210.4,5837.6 4210.4,5801.1 4470.2,5541.3 4565,5447.4 4565,5435 4485,5355 4485,5184.2
  lines w20: 3405,5365 3682.7,5365 3699.5,5348.2 3699.5,5140.2 3709.7,5130 4230,5130 4460,4900 5485,4900 5561,4824 5561,4489 5615,4435 5615,4340 ; 5615,4339.4 5666.6,4287.8 5666.6,4247.2 5696.9,4216.8 5738.4,4216.8 5850.3,4216.8 5910.3,4156.8 5910.3,3968 5780.3,3837.9 5596.7,3837.9 5560,3801.2 5560,3551.9 5636.9,3475 5976.9,3475 6020,3431.9 6020,3158.7

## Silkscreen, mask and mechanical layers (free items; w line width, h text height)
Top Silkscreen Layer:
  drawing of 13 lines, arcs and shapes, not listed
  text "gnd" at 4113.7,5450 h50
  text "scl" at 4215,5450 h50
  text "sda" at 4310,5450 h50
  text "5v" at 4035,5445 h50
  text "gnd" at 4220,5400 h50
  text "clk" at 4030,5395 h50
  text "dio" at 4125,5395 h50
  text "gnd" at 4218.7,5345 h50
  text "3.3" at 4325,5345 h50
  text "rx" at 4045,5340 h50
  text "tx" at 4135,5340 h50
  text "gnd" at 4120,5285 h50
  text "5v" at 4041.8,5280 h50
  text "osi" at 4225,5280 h50
  text "iso" at 4320,5280 h50
  text "sck" at 4410,5280 h50
  text "gnd" at 4038.7,5215 h50
  text "5v" at 4155,5215 h50
  text "scl" at 4250,5215 h50
  text "sda" at 4345,5215 h50
  text "A" at 5920,3405 h120
  text "C" at 5610,3400 h120
  text "B" at 5770,3400 h120
  text "+" at 4245,3394.9 h120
